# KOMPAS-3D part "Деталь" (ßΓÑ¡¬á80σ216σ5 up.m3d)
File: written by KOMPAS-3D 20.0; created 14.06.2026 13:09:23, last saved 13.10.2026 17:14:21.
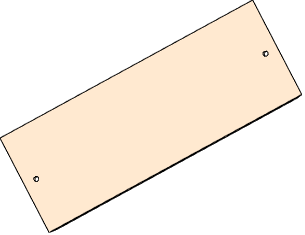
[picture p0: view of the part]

Document properties: Полное имя файла: D:\myProjects\Progect_esp32\box_compas\корпус\стенка80х216х5 up.m3d

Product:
- Part/product: Деталь
    Материал: Фанера, сосна,ФСФ ВВ/С  ГОСТ 3916.2-2018 (density 500 kg/m3)
    Масса: 0.0392703

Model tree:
1. Эскиз:3
2. Элемент выдавливания:4
     Расстояние 1 = 5
3. Эскиз:4  (with: Элемент выдавливания:4)
4. Элемент выдавливания:5
     Расстояние 2 = 216
5. Эскиз:5  (with: Элемент выдавливания:4)
6. Элемент выдавливания:6
     Расстояние 2 = 80
7. Эскиз:6  (with: Элемент выдавливания:4, Элемент выдавливания:6)
8. Элемент выдавливания:7
     Расстояние 2 = 5
9. Массив по сетке:1  (with: Элемент выдавливания:7, Эскиз:6)  (labels: Фанера, сосна,ФСФ ВВ/С  ГОСТ 3916.2-2018)  (2 pattern instances)
     Шаг 1 = 196; Угол раствора = 90; Геометрический массив = 128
